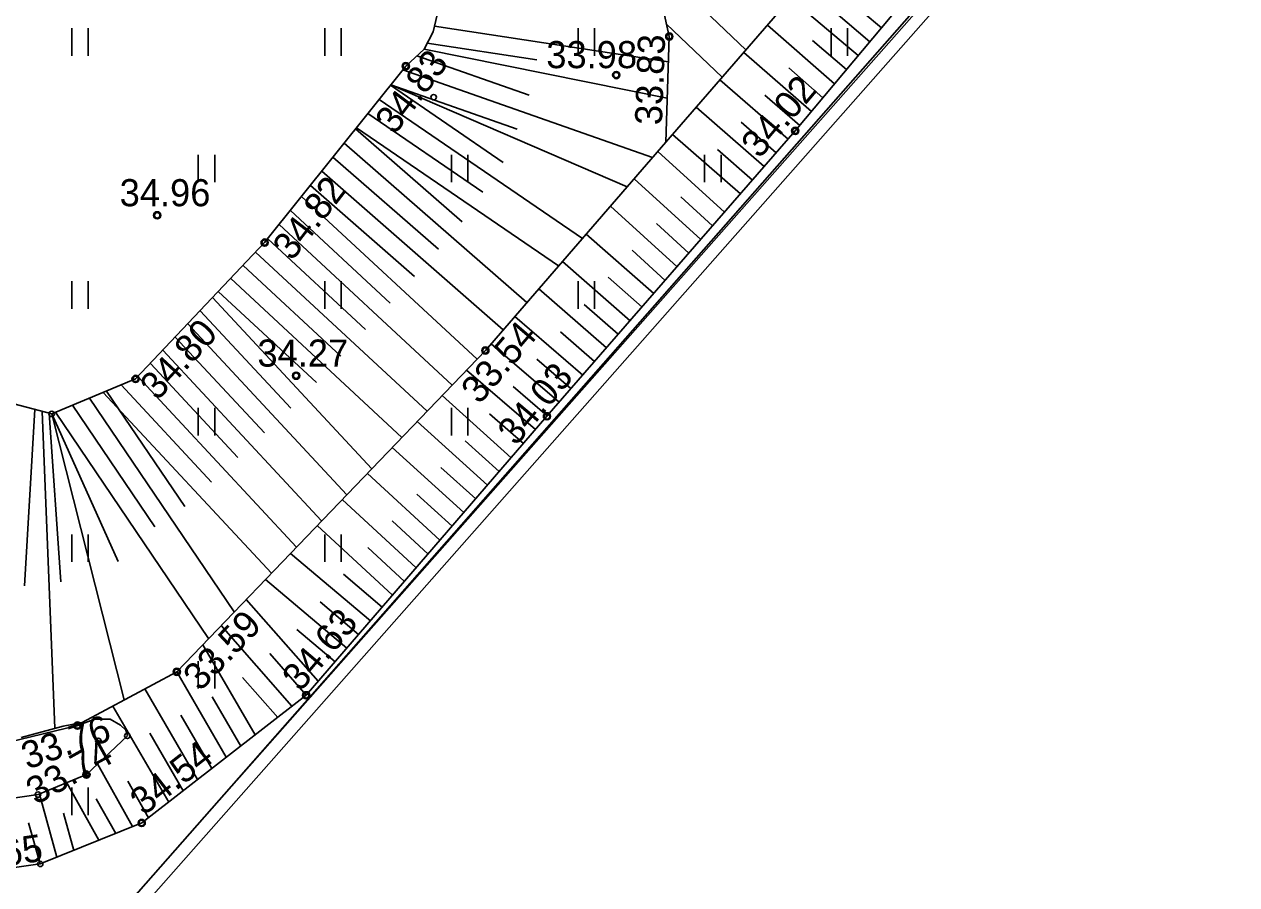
# Model space of a CAD drawing. Extents: x 641898 to 642452, y 6471715 to 6472255.
# Drawn here: x 642090.41 to 642123.94, y 6472108.59 to 6472132.39 of the extents above; entities that cross this region are included whole.
import ezdxf

# ---------------------------------------------------------------- set-up
doc = ezdxf.new("R2010")
doc.units = 0
for name, color, linetype in [('AED', 7, 'Continuous'), ('HALJASTUS', 7, 'Continuous'), ('KORGUS-EH2000', 7, 'Continuous'), ('MOOTMPUNKT', 7, 'Continuous'), ('MOOTPIIR', 7, 'Continuous'), ('PIIR', 7, 'Continuous'), ('RELJEEF', 7, 'Continuous'), ('VEEKOGU', 7, 'Continuous')]:
    doc.layers.add(name, color=color, linetype=linetype)

msp = doc.modelspace()

# ---------------------------------------------------------------- linework, layer by layer
at = {"layer": 'AED'}
msp.add_lwpolyline([(642123.481, 6472142.39), (642081.315, 6472094.482), (642081.931, 6472094.059)], dxfattribs=at)
at = {"layer": 'HALJASTUS'}
for p, q in [((642091.725, 6472132.282), (642091.725, 6472131.521)), ((642092.18, 6472132.282), (642092.18, 6472131.521)), ((642098.725, 6472132.282), (642098.725, 6472131.521)), ((642099.18, 6472132.282), (642099.18, 6472131.521)), ((642105.725, 6472132.282), (642105.725, 6472131.521)), ((642106.18, 6472132.282), (642106.18, 6472131.521)), ((642112.725, 6472132.282), (642112.725, 6472131.521)), ((642113.18, 6472132.282), (642113.18, 6472131.521)), ((642095.225, 6472128.782), (642095.225, 6472128.021)), ((642095.68, 6472128.782), (642095.68, 6472128.021)), ((642102.225, 6472128.782), (642102.225, 6472128.021)), ((642102.68, 6472128.782), (642102.68, 6472128.021)), ((642109.225, 6472128.782), (642109.225, 6472128.021)), ((642109.68, 6472128.782), (642109.68, 6472128.021)), ((642091.725, 6472125.282), (642091.725, 6472124.521)), ((642092.18, 6472125.282), (642092.18, 6472124.521)), ((642098.725, 6472125.282), (642098.725, 6472124.521)), ((642099.18, 6472125.282), (642099.18, 6472124.521)), ((642105.725, 6472125.282), (642105.725, 6472124.521)), ((642106.18, 6472125.282), (642106.18, 6472124.521)), ((642095.225, 6472121.782), (642095.225, 6472121.021)), ((642095.68, 6472121.782), (642095.68, 6472121.021)), ((642102.225, 6472121.782), (642102.225, 6472121.021)), ((642102.68, 6472121.782), (642102.68, 6472121.021)), ((642091.725, 6472118.282), (642091.725, 6472117.521)), ((642092.18, 6472118.282), (642092.18, 6472117.521)), ((642098.725, 6472118.282), (642098.725, 6472117.521)), ((642099.18, 6472118.282), (642099.18, 6472117.521)), ((642095.225, 6472114.782), (642095.225, 6472114.021)), ((642095.68, 6472114.782), (642095.68, 6472114.021)), ((642091.725, 6472111.282), (642091.725, 6472110.521)), ((642092.18, 6472111.282), (642092.18, 6472110.521))]:
    msp.add_line(p, q, dxfattribs=at)
at = {"layer": 'KORGUS-EH2000'}
for centre in [(642108.249, 6472132.052), (642100.963, 6472131.23), (642106.782, 6472130.985), (642111.73, 6472129.44), (642094.09, 6472127.107), (642097.061, 6472126.352), (642103.163, 6472123.369), (642097.931, 6472122.672), (642093.492, 6472122.583), (642104.866, 6472121.549), (642094.632, 6472114.483), (642098.208, 6472113.834), (642091.887, 6472112.996), (642092.133, 6472111.642), (642093.661, 6472110.303)]:
    msp.add_circle(centre, 0.1, dxfattribs=at)
at = {"layer": 'MOOTMPUNKT'}
for centre in [(642108.249, 6472132.052), (642100.963, 6472131.23), (642106.782, 6472130.985), (642101.733, 6472130.372), (642111.73, 6472129.44), (642094.09, 6472127.107), (642097.061, 6472126.352), (642103.163, 6472123.369), (642097.931, 6472122.672), (642093.492, 6472122.583), (642091.173, 6472121.615), (642104.866, 6472121.549), (642094.632, 6472114.483), (642098.208, 6472113.834), (642091.887, 6472112.996), (642092.462, 6472112.574), (642093.264, 6472112.713), (642092.133, 6472111.642), (642090.794, 6472111.089), (642093.661, 6472110.303), (642090.857, 6472109.171)]:
    msp.add_circle(centre, 0.075, dxfattribs=at)
at = {"layer": 'MOOTPIIR'}
msp.add_lwpolyline([(642014.306, 6472085.384), (642027.67, 6472104.979), (642055.501, 6472084.843), (642081.563, 6472094.262), (642123.938, 6472142.273), (642065.721, 6472244.475), (642008.922, 6472196.948), (642003.347, 6472200.453), (641979.65, 6472162.756), (641979.65, 6472162.756), (641986.045, 6472158.736), (642004.269, 6472142.365), (641987.048, 6472123.488), (641970.482, 6472097.889), (641986.758, 6472084.396)], close=True, dxfattribs=at)
at = {"layer": 'PIIR'}
msp.add_line((642081.23, 6472094.44), (642123.61, 6472142.4), dxfattribs=at)
at = {"layer": 'RELJEEF'}
for p, q in [((642107.795, 6472134.13), (642110.368, 6472131.685)), ((642114.115, 6472132.29), (642112.257, 6472133.866)), ((642113.473, 6472131.523), (642111.602, 6472133.11)), ((642113.794, 6472131.906), (642112.852, 6472132.706)), ((642101.76, 6472132.339), (642108.226, 6472131.354)), ((642108.175, 6472132.389), (642109.712, 6472130.928)), ((642112.819, 6472130.742), (642110.96, 6472132.368)), ((642101.553, 6472131.865), (642104.586, 6472131.403)), ((642113.152, 6472131.14), (642112.205, 6472131.943)), ((642101.269, 6472131.518), (642104.374, 6472130.429)), ((642101.467, 6472131.705), (642108.193, 6472130.347)), ((642112.177, 6472129.975), (642110.305, 6472131.612)), ((642100.879, 6472131.125), (642107.785, 6472128.704)), ((642112.498, 6472130.358), (642111.552, 6472131.186)), ((642111.531, 6472129.211), (642109.65, 6472130.856)), ((642100.541, 6472130.702), (642103.655, 6472128.571)), ((642100.548, 6472130.711), (642107.081, 6472127.891)), ((642100.548, 6472130.711), (642104.043, 6472129.486)), ((642111.856, 6472129.591), (642110.894, 6472130.433)), ((642100.228, 6472130.311), (642105.846, 6472126.465)), ((642110.875, 6472128.457), (642108.995, 6472130.101)), ((642099.915, 6472129.919), (642103.09, 6472127.745)), ((642099.575, 6472129.495), (642102.523, 6472126.922)), ((642099.601, 6472129.528), (642105.187, 6472125.705)), ((642111.203, 6472128.834), (642110.235, 6472129.68)), ((642099.263, 6472129.105), (642104.313, 6472124.696)), ((642110.219, 6472127.702), (642108.34, 6472129.345)), ((642109.776, 6472127.193), (642107.931, 6472128.873)), ((642110.547, 6472128.08), (642109.577, 6472128.928)), ((642098.95, 6472128.714), (642101.865, 6472126.169)), ((642098.638, 6472128.323), (642103.658, 6472123.94)), ((642109.119, 6472126.438), (642107.276, 6472128.117)), ((642098.325, 6472127.932), (642101.208, 6472125.416)), ((642098.084, 6472127.631), (642102.935, 6472123.132)), ((642109.447, 6472126.816), (642108.566, 6472127.618)), ((642097.771, 6472127.239), (642100.531, 6472124.679)), ((642108.463, 6472125.684), (642106.621, 6472127.361)), ((642097.458, 6472126.848), (642102.242, 6472122.41)), ((642108.791, 6472126.061), (642107.893, 6472126.879)), ((642097.145, 6472126.456), (642099.851, 6472123.946)), ((642107.822, 6472124.947), (642105.951, 6472126.586)), ((642096.809, 6472126.086), (642101.55, 6472121.689)), ((642108.134, 6472125.306), (642107.219, 6472126.14)), ((642096.465, 6472125.723), (642099.171, 6472123.213)), ((642107.166, 6472124.193), (642105.296, 6472125.831)), ((642107.494, 6472124.57), (642106.556, 6472125.392)), ((642096.121, 6472125.36), (642100.857, 6472120.967)), ((642106.51, 6472123.438), (642104.641, 6472125.075)), ((642095.622, 6472124.832), (642100.024, 6472120.099)), ((642095.777, 6472124.997), (642098.491, 6472122.48)), ((642095.278, 6472124.469), (642097.785, 6472121.773)), ((642106.838, 6472123.816), (642105.897, 6472124.639)), ((642094.933, 6472124.105), (642099.33, 6472119.377)), ((642105.859, 6472122.69), (642103.981, 6472124.313)), ((642094.589, 6472123.741), (642097.053, 6472121.092)), ((642106.181, 6472123.061), (642105.238, 6472123.887)), ((642094.244, 6472123.377), (642098.637, 6472118.654)), ((642105.202, 6472121.936), (642103.326, 6472123.557)), ((642105.53, 6472122.313), (642104.583, 6472123.132)), ((642093.9, 6472123.013), (642096.32, 6472120.411)), ((642104.547, 6472121.18), (642102.642, 6472122.827)), ((642093.09, 6472122.415), (642095.588, 6472119.73)), ((642093.555, 6472122.65), (642097.943, 6472117.932)), ((642104.874, 6472121.558), (642103.929, 6472122.375)), ((642092.22, 6472122.052), (642096.221, 6472116.138)), ((642092.598, 6472122.21), (642097.249, 6472117.209)), ((642092.69, 6472122.248), (642094.85, 6472119.056)), ((642103.875, 6472120.401), (642101.97, 6472122.126)), ((642090.705, 6472121.738), (642090.422, 6472116.86)), ((642091.749, 6472121.855), (642094.022, 6472118.495)), ((642090.907, 6472121.685), (642091.26, 6472112.922)), ((642091.1, 6472121.634), (642091.422, 6472116.97)), ((642091.173, 6472121.615), (642093.014, 6472117.532)), ((642091.173, 6472121.615), (642093.18, 6472113.705)), ((642091.278, 6472121.659), (642095.512, 6472115.4)), ((642103.221, 6472119.643), (642101.277, 6472121.405)), ((642104.221, 6472120.801), (642103.275, 6472121.619)), ((642102.568, 6472118.886), (642100.584, 6472120.683)), ((642103.548, 6472120.022), (642102.608, 6472120.874)), ((642102.895, 6472119.265), (642101.936, 6472120.133)), ((642101.907, 6472118.12), (642099.9, 6472119.97)), ((642102.241, 6472118.507), (642101.265, 6472119.392)), ((642101.253, 6472117.362), (642099.207, 6472119.249)), ((642100.599, 6472116.605), (642098.515, 6472118.527)), ((642101.58, 6472117.741), (642100.587, 6472118.657)), ((642099.986, 6472115.894), (642097.777, 6472117.759)), ((642100.926, 6472116.984), (642099.909, 6472117.922)), ((642099.333, 6472115.137), (642097.083, 6472117.036)), ((642100.313, 6472116.273), (642099.237, 6472117.181)), ((642098.541, 6472114.22), (642096.553, 6472116.484)), ((642099.659, 6472115.516), (642098.592, 6472116.417)), ((642097.816, 6472113.53), (642095.858, 6472115.76)), ((642099.006, 6472114.759), (642097.947, 6472115.653)), ((642096.798, 6472112.739), (642095.352, 6472115.233)), ((642098.211, 6472113.838), (642097.201, 6472114.988)), ((642096.001, 6472112.12), (642094.631, 6472114.483)), ((642097.421, 6472113.222), (642096.449, 6472114.328)), ((642095.204, 6472111.501), (642093.749, 6472114.01)), ((642096.4, 6472112.43), (642095.613, 6472113.787)), ((642094.407, 6472110.882), (642092.867, 6472113.537)), ((642095.603, 6472111.811), (642094.747, 6472113.285)), ((642094.806, 6472111.192), (642093.882, 6472112.784)), ((642093.41, 6472110.202), (642092.443, 6472111.935)), ((642092.475, 6472109.824), (642091.587, 6472111.416)), ((642093.846, 6472110.446), (642093.279, 6472111.461)), ((642091.317, 6472109.357), (642090.831, 6472111.104)), ((642092.943, 6472110.013), (642092.406, 6472110.974)), ((642090.85, 6472109.17), (642090.534, 6472110.306)), ((642091.783, 6472109.545), (642091.497, 6472110.573))]:
    msp.add_line(p, q, dxfattribs=at)
for points in [[(642088.203, 6472153.512), (642093.496, 6472152.442), (642098.936, 6472148.247), (642104.078, 6472143.474), (642106.771, 6472138.81), (642108.249, 6472132.052), (642108.153, 6472129.129), (642103.163, 6472123.369), (642094.632, 6472114.483), (642092.016, 6472113.081)], [(642101.723, 6472132.18), (642101.943, 6472133.131), (642101.711, 6472134.384), (642101.053, 6472138.133), (642098.3, 6472141.719), (642094.79, 6472145.415), (642092.349, 6472145.794), (642088.003, 6472144.291), (642078.92, 6472140.224), (642077.008, 6472138.651), (642077.72, 6472135.256), (642081.31, 6472131.799), (642085.536, 6472126.79), (642089.101, 6472122.158), (642091.173, 6472121.615), (642093.492, 6472122.583), (642097.061, 6472126.352), (642100.963, 6472131.23), (642101.467, 6472131.705), (642101.723, 6472132.18)], [(642121.483, 6472144.248), (642114.271, 6472136.19), (642108.156, 6472129.132)], [(642123.464, 6472142.672), (642123.047, 6472142.573), (642120.087, 6472139.168), (642115.741, 6472134.233), (642111.73, 6472129.44), (642104.866, 6472121.549), (642098.208, 6472113.834), (642093.661, 6472110.303), (642090.857, 6472109.171), (642088.254, 6472108.802), (642086.484, 6472109.321), (642083.076, 6472111.816), (642080.848, 6472115.189), (642078.612, 6472117.548), (642074.153, 6472119.305), (642067.802, 6472127.345), (642067.041, 6472129.467)], [(642092.016, 6472113.081), (642091.487, 6472112.976), (642090.327, 6472112.663)]]:
    msp.add_lwpolyline(points, dxfattribs=at)
at = {"layer": 'VEEKOGU'}
for points in [[(642066.18, 6472132.576), (642073.243, 6472127.488), (642080.634, 6472121.195), (642083.462, 6472118.175), (642085.565, 6472115.242), (642087.183, 6472113.461), (642088.47, 6472112.631), (642089.988, 6472112.534), (642091.887, 6472112.996), (642092.366, 6472113.174), (642092.788, 6472113.174), (642093.075, 6472113.004), (642093.218, 6472112.874), (642093.267, 6472112.716)], [(642093.267, 6472112.716), (642092.133, 6472111.642), (642090.794, 6472111.089), (642089.396, 6472110.889), (642087.889, 6472111.257), (642086.642, 6472112.02), (642085.093, 6472113.357), (642082.95, 6472116.352), (642081.022, 6472118.598), (642079.591, 6472119.867), (642077.142, 6472121.148), (642075.647, 6472121.903), (642071.926, 6472125.922), (642067.041, 6472129.467)]]:
    msp.add_lwpolyline(points, dxfattribs=at)

# ---------------------------------------------------------------- texts
at = {"layer": 'KORGUS-EH2000'}
for s, p in [('33.98', (642104.848, 6472131.175)), ('34.96', (642093.051, 6472127.357)), ('34.27', (642096.86, 6472122.922))]:
    msp.add_text(s, height=0.75, dxfattribs=at).set_placement(p)
for s, rotation, p in [('33.83', 87.8836, (642108.044, 6472129.591)), ('34.83', 52.9171, (642100.658, 6472129.31)), ('34.02', 49.7234, (642110.745, 6472128.648)), ('34.82', 52.307, (642097.819, 6472125.819)), ('34.80', 47.2051, (642094.098, 6472121.958)), ('33.54', 49.4188, (642102.999, 6472121.855)), ('34.03', 49.8327, (642104.01, 6472120.705)), ('33.59', 46.2266, (642095.281, 6472113.921)), ('34.63', 49.7261, (642098.053, 6472113.909)), ('33.76', 19.3644, (642090.499, 6472111.776)), ('33.74', 28.9831, (642090.736, 6472110.789)), ('34.54', 38.0148, (642093.72, 6472110.49)), ('34.65', 8.2642, (642088.478, 6472108.899))]:
    msp.add_text(s, height=0.75, rotation=rotation, dxfattribs=at).set_placement(p)

doc.saveas('drawing.dxf')
